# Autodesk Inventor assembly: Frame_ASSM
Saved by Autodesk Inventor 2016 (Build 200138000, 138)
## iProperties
Created: 2015-11
Part Number: Frame_ASSM
Document SubType Name: Assembly
Designer: John
Author: John
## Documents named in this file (8)
- D:\3D Printer Designs\John Ledden Designs\DLP Printer\V0-4\Frame_ASSM.iam
- D:\3D Printer Designs\John Ledden Designs\DLP Printer\V0-4\Frame_RSide.ipt
- D:\3D Printer Designs\John Ledden Designs\DLP Printer\V0-4\Frame_LSide.ipt
- D:\3D Printer Designs\John Ledden Designs\DLP Printer\V0-4\Frame_Front.ipt
- D:\3D Printer Designs\John Ledden Designs\DLP Printer\V0-4\M5_Nut.ipt
- D:\3D Printer Designs\John Ledden Designs\DLP Printer\V0-4\M5_30.ipt
- D:\3D Printer Designs\John Ledden Designs\DLP Printer\V0-4\PROJECTOR_BACK.iam
- D:\3D Printer Designs\John Ledden Designs\DLP Printer\V0-4\PROJECTOR_UNDER.iam
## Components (39 placed, 39 different names)
1. Frame_RSide_1031
2. Frame_LSide_1032
3. Frame_Front_1033
4. M5_Nut_1034
5. M5_30_1035
6. M5_30_1036
7. M5_30_1037
8. M5_30_1038
9. M5_30_1039
10. M5_30_1040
11. M5_30_1041
12. M5_30_1042
13. M5_30_1043
14. M5_30_1044
15. M5_30_1045
16. M5_30_1046
17. M5_30_1047
18. M5_30_1048
19. M5_30_1049
20. M5_30_1050
21. M5_30_1051
22. M5_Nut_1052
23. M5_Nut_1053
24. M5_Nut_1054
25. M5_Nut_1055
26. M5_Nut_1056
27. M5_Nut_1057
28. M5_Nut_1058
29. M5_Nut_1059
30. M5_Nut_1060
31. M5_Nut_1061
32. M5_Nut_1062
33. M5_Nut_1063
34. M5_Nut_1064
35. M5_Nut_1065
36. M5_Nut_1066
37. M5_Nut_1067
38. PROJECTOR_BACK_1068 [sub-assembly]
39. PROJECTOR_UNDER_1069 [sub-assembly]
